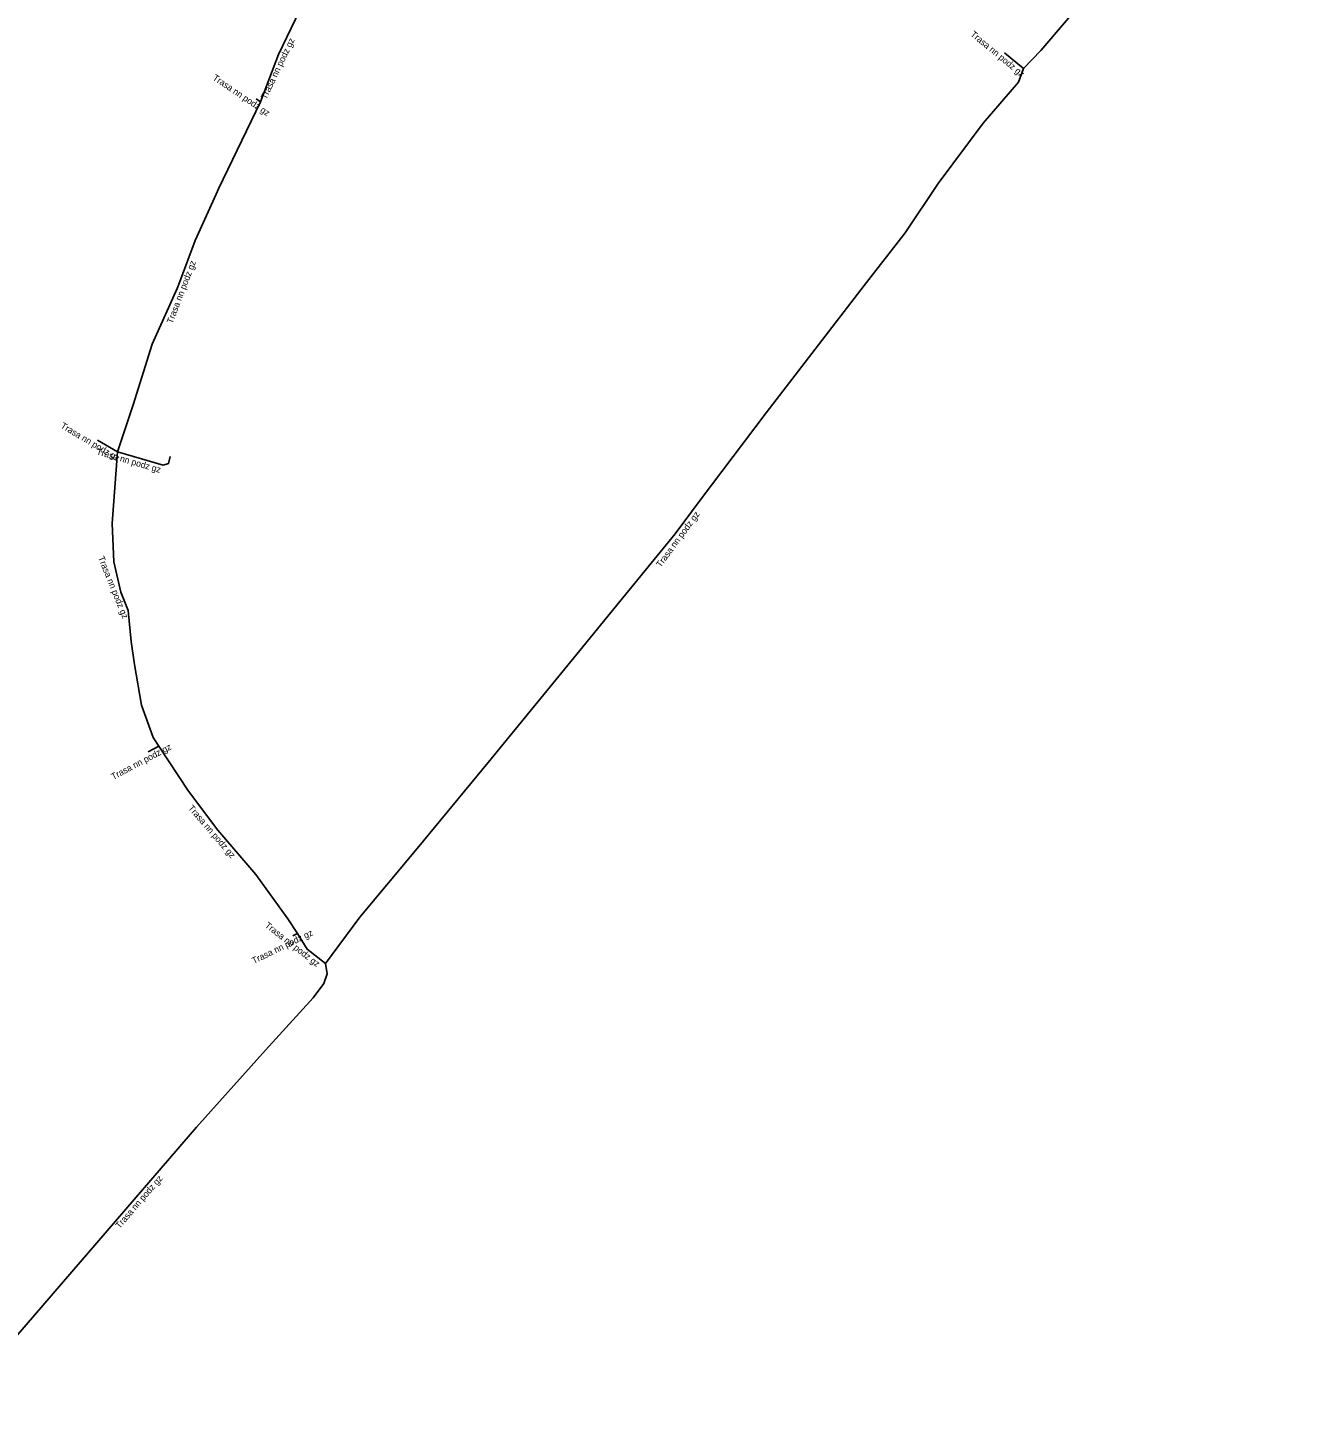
# Model space of a CAD drawing. Extents: x -747130 to -746834, y -1018555 to -1017941.
# Drawn here: x -747024.9 to -746925, y -1018387.8 to -1018281 of the extents above; entities that cross this region are included whole.
import ezdxf

# ---------------------------------------------------------------- set-up
doc = ezdxf.new("R2010")
doc.units = 0
doc.layers.add('Popiskový text - Ostatní atributy Trasy', color=7, linetype='Continuous')
doc.layers.add('Spojnice NN', color=7, linetype='Continuous')

msp = doc.modelspace()

# ---------------------------------------------------------------- linework, layer by layer
at = {"layer": 'Spojnice NN'}
for points in [[(-746947.65, -1018284.16), (-746946.3, -1018282.75), (-746942.47, -1018278.26), (-746936, -1018270.89), (-746932.54, -1018267.26), (-746928, -1018262.35), (-746924.98, -1018259.25)], [(-747006.86, -1018286.75), (-747005.46, -1018283.08), (-747003.51, -1018278.98)], [(-746949.12, -1018282.95), (-746947.65, -1018284.16)], [(-747001.81, -1018353.62), (-746999.14, -1018350.03), (-746994.7, -1018344.69), (-746989.19, -1018338.02), (-746981.83, -1018329.05), (-746979.9, -1018326.67), (-746974.67, -1018320.28), (-746972.74, -1018317.65), (-746967.61, -1018310.89), (-746960.01, -1018301), (-746956.83, -1018296.91), (-746954.26, -1018293.08), (-746950.78, -1018288.41), (-746948.03, -1018285.22), (-746947.65, -1018284.16)], [(-747017.97, -1018313.91), (-747016.75, -1018310.27), (-747015.26, -1018305.55), (-747013.33, -1018301.22), (-747013.16, -1018300.77), (-747011.92, -1018297.5), (-747010.3, -1018293.91), (-747010.13, -1018293.49), (-747006.86, -1018286.75)], [(-747007.2, -1018286.52), (-747006.86, -1018286.75)], [(-747019.52, -1018312.99), (-747017.97, -1018313.91)], [(-747014.74, -1018336.76), (-747015.18, -1018336.08), (-747016.1, -1018333.57), (-747016.65, -1018330.41), (-747016.91, -1018328.63), (-747017.12, -1018326.22), (-747017.69, -1018324.81), (-747018.24, -1018322.44), (-747018.37, -1018319.48), (-747017.97, -1018313.91)], [(-747017.97, -1018313.91), (-747014.41, -1018314.95), (-747014.01, -1018314.82), (-747013.86, -1018314.26)], [(-747014.74, -1018336.76), (-747015.57, -1018337.2)], [(-747003.98, -1018351.28), (-747004.75, -1018350.15), (-747007.22, -1018346.71), (-747010.18, -1018343.28), (-747012.46, -1018340.25), (-747014.74, -1018336.76)], [(-747003.98, -1018351.28), (-747004.35, -1018351.46)], [(-747001.81, -1018353.62), (-747003.24, -1018352.51), (-747003.98, -1018351.28)], [(-747030.49, -1018387.84), (-747025.86, -1018382.59), (-747018.77, -1018374.36), (-747011.83, -1018366.33), (-747006.47, -1018360.35), (-747002.76, -1018356.27), (-747001.95, -1018355.16), (-747001.69, -1018354.42), (-747001.81, -1018353.62)]]:
    msp.add_lwpolyline(points, dxfattribs=at)

# ---------------------------------------------------------------- texts
at = {"layer": 'Popiskový text - Ostatní atributy Trasy'}
for rotation, p in [(320.5412, (-746951.8, -1018281.58)), (64.5638, (-747006.41, -1018286.6)), (325.9228, (-747010.62, -1018284.99)), (69.233, (-747013.69, -1018304)), (329.3088, (-747022.42, -1018312.02)), (343.7151, (-747019.63, -1018314.1)), (53.7273, (-746975.8, -1018322.92)), (292.0113, (-747019.48, -1018322.12)), (27.929, (-747018.29, -1018339.38)), (310.7933, (-747012.51, -1018341.58)), (25.9423, (-747007.38, -1018353.66)), (322.1805, (-747006.57, -1018350.75)), (49.1645, (-747017.8, -1018374.23))]:
    msp.add_text('Trasa nn podz gz', height=0.5, rotation=rotation, dxfattribs=at).set_placement(p)

doc.saveas('drawing.dxf')
